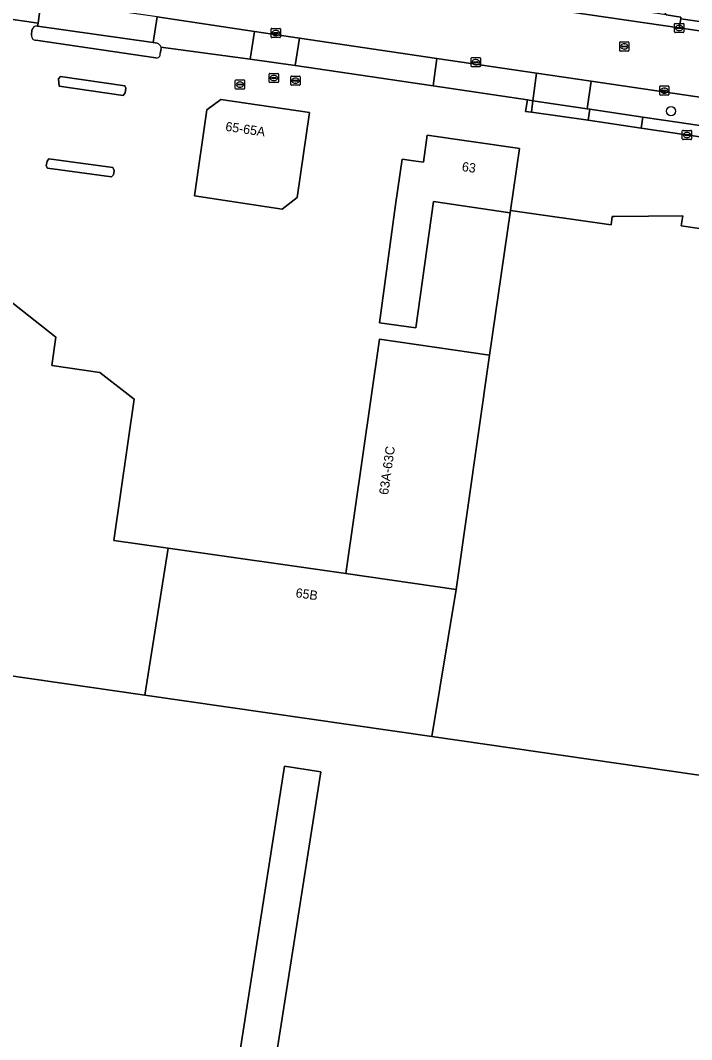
# Model space of a CAD drawing. Extents: x 163683 to 164494, y 382709 to 383872.
# Drawn here: x 163904.3 to 163976.8, y 382819.4 to 382929.4 of the extents above; entities that cross this region are included whole.
import ezdxf

# ---------------------------------------------------------------- set-up
doc = ezdxf.new("R2010")
doc.units = 0
for name, color, linetype in [('IMGEO_Berm_groen', 7, 'Continuous'), ('IMGEO_Boom', 7, 'Continuous'), ('IMGEO_Erf', 7, 'Continuous'), ('IMGEO_Groenvoorziening', 7, 'Continuous'), ('IMGEO_Kolk', 7, 'Continuous'), ('IMGEO_Pand', 7, 'Continuous'), ('IMGEO_Pand_nummerreeks', 7, 'Continuous'), ('IMGEO_Parkeervlak_open', 7, 'Continuous'), ('IMGEO_Rijbaan_lokaal_gesloten', 7, 'Continuous'), ('IMGEO_Rioolput', 7, 'Continuous'), ('IMGEO_Terreindeel_open', 7, 'Continuous'), ('IMGEO_Verkeerseiland_open', 7, 'Continuous'), ('IMGEO_Voetpad_open', 7, 'Continuous')]:
    doc.layers.add(name, color=color, linetype=linetype)

msp = doc.modelspace()

# ---------------------------------------------------------------- linework, layer by layer
at = {"layer": 'IMGEO_Berm_groen'}
msp.add_lwpolyline([(163977.61, 382933.57), (163972.72, 382934.26), (163972.46, 382932.41), (163974.04, 382930.02), (163975.63, 382929.77), (163975.61, 382929.56), (163989.46, 382927.61), (163987.76, 382928.27), (163985.01, 382929.59), (163980.27, 382932.49)], dxfattribs=at)
at = {"layer": 'IMGEO_Boom'}
msp.add_circle((163974.55, 382919.61), 0.489, dxfattribs=at)
at = {"layer": 'IMGEO_Erf'}
for points in [[(163906.13, 382928.79), (163906.23, 382929.1), (163890.65, 382931.38)], [(163905.49, 382927.8), (163905.54, 382928.4)], [(163918.92, 382925.37), (163905.96, 382927.26)], [(163919.49, 382926.34), (163919.38, 382925.85)], [(164013.55, 382911.55), (163971.34, 382917.77), (163965.62, 382918.65), (163959.5, 382919.49), (163958.85, 382919.58), (163959.06, 382920.84), (163948.86, 382922.34), (163933.98, 382924.53), (163929.13, 382925.24), (163919.48, 382926.52)], [(163944.79, 382909.49), (163945.51, 382914.44), (163946.75, 382914.26), (163947.82, 382914.1), (163948.24, 382917.02), (163957.99, 382915.6), (163958.21, 382915.57), (163957.24, 382908.9), (163968.09, 382907.35), (163968.21, 382908.23), (163968.41, 382908.23), (163975.83, 382908.31), (163975.66, 382907.23), (163979.1, 382906.72)], [(163902.97, 382899.27), (163908.12, 382895.2), (163907.71, 382892.14), (163912.87, 382891.39), (163916.57, 382888.53), (163914.4, 382873.28), (163920.25, 382872.44), (163939.45, 382869.7), (163943.07, 382894.99), (163954.97, 382893.26), (163957.2, 382908.65), (163948.9, 382909.85), (163947.02, 382896.22), (163943.07, 382896.77), (163944.79, 382909.49)]]:
    msp.add_lwpolyline(points, dxfattribs=at)
for points in [[(163915.4, 382921.31), (163908.48, 382922.31), (163908.43, 382923.1), (163908.62, 382923.34), (163915.56, 382922.34), (163915.67, 382922.08), (163915.6, 382921.58)], [(163923.11, 382910.46), (163924.45, 382919.77), (163925.94, 382920.88), (163935.52, 382919.48), (163934.18, 382910.29), (163932.55, 382909.05)], [(163914.14, 382912.51), (163907.21, 382913.44), (163907.09, 382913.72), (163907.18, 382914.23), (163907.37, 382914.46), (163914.29, 382913.52), (163914.42, 382913.22), (163914.34, 382912.73)]]:
    msp.add_lwpolyline(points, close=True, dxfattribs=at)
for centre, radius, start, end in [((163906.05, 382928.27), 0.523, 80.6392, 165.5717), ((163906, 382927.76), 0.505, 174.9914, 265.5189), ((163919.05, 382926.42), 0.445, 349.7444, 12.8302), ((163919.03, 382925.73), 0.368, 252.9197, 19.298)]:
    msp.add_arc(centre, radius, start, end, dxfattribs=at)
at = {"layer": 'IMGEO_Groenvoorziening'}
msp.add_lwpolyline([(164000, 382844.71), (163948.74, 382852.1), (163917.73, 382856.57), (163880.83, 382861.88), (163850.77, 382866.24), (163850.46, 382866.29), (163830.96, 382869.23), (163833.62, 382887.2), (163833.33, 382887.25), (163823.99, 382888.59), (163821.09, 382869.09), (163813.85, 382820.4)], dxfattribs=at)
msp.add_lwpolyline([(163932.82, 382848.91), (163936.73, 382848.3), (163931.09, 382812.33), (163927.19, 382812.94)], close=True, dxfattribs=at)
at = {"layer": 'IMGEO_Kolk'}
for p, q in [((163931.38, 382927.62), (163931.38, 382928.48)), ((163931.45, 382928.55), (163932.3, 382928.55)), ((163932.38, 382928.48), (163932.38, 382927.62)), ((163974.93, 382928.16), (163974.93, 382929.02)), ((163975.01, 382929.09), (163975.86, 382929.09)), ((163975.19, 382928.58), (163975.19, 382928.6)), ((163975.63, 382928.55), (163975.23, 382928.55)), ((163975.24, 382928.63), (163975.63, 382928.63)), ((163975.42, 382928.87), (163975.45, 382928.87)), ((163975.68, 382928.6), (163975.68, 382928.58)), ((163975.94, 382929.02), (163975.94, 382928.16)), ((163932.3, 382927.55), (163931.45, 382927.55)), ((163931.64, 382928.04), (163931.64, 382928.06)), ((163931.68, 382928.09), (163932.08, 382928.09)), ((163932.07, 382928.01), (163931.68, 382928.01)), ((163931.89, 382927.77), (163931.86, 382927.77)), ((163931.87, 382928.33), (163931.89, 382928.33)), ((163932.12, 382928.06), (163932.12, 382928.04)), ((163975.86, 382928.09), (163975.01, 382928.09)), ((163975.44, 382928.31), (163975.42, 382928.31)), ((163952.98, 382924.48), (163952.98, 382925.33)), ((163953.05, 382925.4), (163953.9, 382925.4)), ((163953.47, 382925.18), (163953.49, 382925.18)), ((163953.98, 382925.33), (163953.98, 382924.48)), ((163953.9, 382924.4), (163953.05, 382924.4)), ((163953.24, 382924.9), (163953.24, 382924.91)), ((163953.28, 382924.95), (163953.68, 382924.95)), ((163953.67, 382924.86), (163953.28, 382924.86)), ((163953.49, 382924.62), (163953.46, 382924.62)), ((163953.72, 382924.91), (163953.72, 382924.9)), ((163973.34, 382921.4), (163973.34, 382922.26)), ((163973.41, 382922.33), (163974.27, 382922.33)), ((163973.64, 382921.87), (163974.04, 382921.87)), ((163973.83, 382922.11), (163973.85, 382922.11)), ((163974.34, 382922.26), (163974.34, 382921.4)), ((163974.27, 382921.33), (163973.41, 382921.33)), ((163973.6, 382921.82), (163973.6, 382921.84)), ((163974.03, 382921.79), (163973.64, 382921.79)), ((163973.85, 382921.55), (163973.82, 382921.55)), ((163974.08, 382921.84), (163974.08, 382921.82)), ((163975.78, 382916.62), (163975.78, 382917.47)), ((163975.86, 382917.54), (163976.71, 382917.54)), ((163976.78, 382917.47), (163976.78, 382916.62)), ((163976.71, 382916.54), (163975.86, 382916.54)), ((163976.04, 382917.04), (163976.04, 382917.05)), ((163976.48, 382917), (163976.08, 382917)), ((163976.09, 382917.09), (163976.48, 382917.09)), ((163976.27, 382917.32), (163976.3, 382917.32)), ((163976.29, 382916.76), (163976.27, 382916.76)), ((163976.53, 382917.05), (163976.53, 382917.04))]:
    msp.add_line(p, q, dxfattribs=at)
for points in [[(163931.38, 382927.62), (163931.38, 382928.48)], [(163931.45, 382928.55), (163932.3, 382928.55)], [(163932.38, 382928.48), (163932.38, 382927.62)], [(163974.93, 382928.16), (163974.93, 382929.02)], [(163975.01, 382929.09), (163975.86, 382929.09)], [(163975.94, 382929.02), (163975.94, 382928.16)], [(163932.3, 382927.55), (163931.45, 382927.55)], [(163975.86, 382928.09), (163975.01, 382928.09)], [(163952.98, 382924.48), (163952.98, 382925.33)], [(163953.05, 382925.4), (163953.9, 382925.4)], [(163953.98, 382925.33), (163953.98, 382924.48)], [(163953.9, 382924.4), (163953.05, 382924.4)], [(163973.34, 382921.4), (163973.34, 382922.26)], [(163973.41, 382922.33), (163974.27, 382922.33)], [(163974.34, 382922.26), (163974.34, 382921.4)], [(163974.27, 382921.33), (163973.41, 382921.33)], [(163975.78, 382916.62), (163975.78, 382917.47)], [(163975.86, 382917.54), (163976.71, 382917.54)], [(163976.78, 382917.47), (163976.78, 382916.62)], [(163976.71, 382916.54), (163975.86, 382916.54)]]:
    msp.add_lwpolyline(points, dxfattribs=at)
for centre, radius, start, end in [((163931.45, 382928.47), 0.0765, 91.552, 178.448), ((163931.45, 382928.47), 0.0765, 91.552, 178.448), ((163932.3, 382928.47), 0.0765, 1.552, 88.448), ((163932.3, 382928.47), 0.0765, 1.552, 88.448), ((163975.01, 382929.02), 0.0765, 91.552, 178.448), ((163975.01, 382929.02), 0.0765, 91.552, 178.448), ((163975.23, 382928.59), 0.0403, 85.8775, 175.7526), ((163975.23, 382928.58), 0.0366, 178.938, 274.7102), ((163975.64, 382928.6), 0.0386, 1.7309, 96.639), ((163975.63, 382928.59), 0.043, 264.8664, 352.4533), ((163975.86, 382929.02), 0.0765, 1.552, 88.448), ((163975.86, 382929.02), 0.0765, 1.552, 88.448), ((163931.45, 382927.63), 0.0765, 181.552, 268.448), ((163931.45, 382927.63), 0.0765, 181.552, 268.448), ((163931.68, 382928.05), 0.0403, 85.8775, 175.7526), ((163931.67, 382928.04), 0.0366, 178.938, 274.7102), ((163932.08, 382928.05), 0.043, 264.8664, 352.4533), ((163932.08, 382928.05), 0.0386, 1.7309, 96.639), ((163932.3, 382927.63), 0.0765, 271.552, 358.448), ((163932.3, 382927.63), 0.0765, 271.552, 358.448), ((163975.01, 382928.17), 0.0765, 181.552, 268.448), ((163975.01, 382928.17), 0.0765, 181.552, 268.448), ((163975.86, 382928.17), 0.0765, 271.552, 358.448), ((163975.86, 382928.17), 0.0765, 271.552, 358.448), ((163953.05, 382925.33), 0.0765, 91.552, 178.448), ((163953.05, 382925.33), 0.0765, 91.552, 178.448), ((163953.9, 382925.33), 0.0765, 1.552, 88.448), ((163953.9, 382925.33), 0.0765, 1.552, 88.448), ((163953.05, 382924.48), 0.0765, 181.552, 268.448), ((163953.05, 382924.48), 0.0765, 181.552, 268.448), ((163953.28, 382924.91), 0.0403, 85.8775, 175.7526), ((163953.27, 382924.9), 0.0366, 178.938, 274.7102), ((163953.68, 382924.9), 0.043, 264.8664, 352.4533), ((163953.68, 382924.91), 0.0386, 1.7309, 96.639), ((163953.9, 382924.48), 0.0765, 271.552, 358.448), ((163953.9, 382924.48), 0.0765, 271.552, 358.448), ((163973.41, 382922.25), 0.0765, 91.552, 178.448), ((163973.41, 382922.25), 0.0765, 91.552, 178.448), ((163973.64, 382921.83), 0.0403, 85.8775, 175.7526), ((163974.04, 382921.83), 0.0386, 1.7309, 96.639), ((163974.26, 382922.25), 0.0765, 1.552, 88.448), ((163974.26, 382922.25), 0.0765, 1.552, 88.448), ((163973.41, 382921.41), 0.0765, 181.552, 268.448), ((163973.41, 382921.41), 0.0765, 181.552, 268.448), ((163973.63, 382921.82), 0.0366, 178.938, 274.7102), ((163974.04, 382921.83), 0.043, 264.8664, 352.4533), ((163974.26, 382921.41), 0.0765, 271.552, 358.448), ((163974.26, 382921.41), 0.0765, 271.552, 358.448), ((163975.86, 382917.47), 0.0765, 91.552, 178.448), ((163975.86, 382917.47), 0.0765, 91.552, 178.448), ((163976.71, 382917.47), 0.0765, 1.552, 88.448), ((163976.71, 382917.47), 0.0765, 1.552, 88.448), ((163975.86, 382916.62), 0.0765, 181.552, 268.448), ((163975.86, 382916.62), 0.0765, 181.552, 268.448), ((163976.08, 382917.05), 0.0403, 85.8775, 175.7526), ((163976.08, 382917.04), 0.0366, 178.938, 274.7102), ((163976.49, 382917.05), 0.0386, 1.7309, 96.639), ((163976.48, 382917.04), 0.043, 264.8664, 352.4533), ((163976.71, 382916.62), 0.0765, 271.552, 358.448), ((163976.71, 382916.62), 0.0765, 271.552, 358.448)]:
    msp.add_arc(centre, radius, start, end, dxfattribs=at)
for centre, major_axis, ratio, start_param, end_param in [((163975.42, 382928.59), (-0.387, 0.002), 0.722429, 4.712389, 7.853982), ((163975.45, 382928.59), (-0.39, 0.002), 0.717154, 1.570796, 4.712389), ((163931.86, 382928.05), (-0.387, 0.002), 0.722429, 4.712389, 7.853982), ((163931.89, 382928.05), (-0.39, 0.002), 0.717154, 1.570796, 4.712389), ((163953.46, 382924.9), (-0.387, 0.002), 0.722429, 4.712389, 7.853982), ((163953.49, 382924.9), (-0.39, 0.002), 0.717154, 1.570796, 4.712389), ((163973.83, 382921.83), (-0.387, 0.002), 0.722429, 4.712389, 7.853982), ((163973.85, 382921.83), (-0.39, 0.002), 0.717154, 1.570796, 4.712389), ((163976.27, 382917.04), (-0.387, 0.002), 0.722429, 4.712389, 7.853982), ((163976.29, 382917.04), (-0.39, 0.002), 0.717154, 1.570796, 4.712389)]:
    msp.add_ellipse(centre, major_axis=major_axis, ratio=ratio, start_param=start_param, end_param=end_param, dxfattribs=at)
at = {"layer": 'IMGEO_Pand'}
for points in [[(163932.55, 382909.05), (163934.18, 382910.29), (163935.52, 382919.48), (163925.94, 382920.88), (163924.45, 382919.77), (163923.11, 382910.46)], [(163958.21, 382915.57), (163957.99, 382915.6), (163948.24, 382917.02), (163947.82, 382914.1), (163946.75, 382914.26), (163945.51, 382914.44), (163944.79, 382909.49), (163943.07, 382896.77), (163947.02, 382896.22), (163948.9, 382909.85), (163957.2, 382908.65), (163957.24, 382908.9)], [(164012.05, 382900.87), (164000, 382902.64), (163979.22, 382905.69), (163978.95, 382905.73), (163979.1, 382906.72), (163975.66, 382907.23), (163975.83, 382908.31), (163968.41, 382908.23), (163968.21, 382908.23), (163968.09, 382907.35), (163957.24, 382908.9), (163957.2, 382908.65), (163954.97, 382893.26), (163951.34, 382867.97), (163948.74, 382852.1), (164000, 382844.71), (164003.76, 382844.17), (164005.06, 382853.08), (164006.91, 382865.72)], [(163917.73, 382856.57), (163920.25, 382872.44), (163914.4, 382873.28), (163916.57, 382888.53), (163912.87, 382891.39), (163907.71, 382892.14), (163908.12, 382895.2), (163902.97, 382899.27), (163896.74, 382896.84), (163896.27, 382893.82), (163891.18, 382894.5), (163886.72, 382892.72), (163884.5, 382877.5), (163883.13, 382877.69), (163882.41, 382872.74), (163880.83, 382861.88)], [(163939.45, 382869.7), (163951.34, 382867.97), (163954.97, 382893.26), (163943.07, 382894.99)], [(163939.45, 382869.7), (163920.25, 382872.44), (163917.73, 382856.57), (163948.74, 382852.1), (163951.34, 382867.97)]]:
    msp.add_lwpolyline(points, close=True, dxfattribs=at)
at = {"layer": 'IMGEO_Parkeervlak_open'}
for points in [[(163919.07, 382929.78), (163906.56, 382931.62), (163906.23, 382929.1), (163906.13, 382928.79), (163918.64, 382927.02)], [(163934.45, 382927.5), (163929.58, 382928.22), (163929.13, 382925.24), (163933.98, 382924.53)], [(163960.03, 382923.72), (163949.27, 382925.31), (163948.86, 382922.34), (163959.06, 382920.84), (163959.62, 382920.74)]]:
    msp.add_lwpolyline(points, close=True, dxfattribs=at)
msp.add_lwpolyline([(164021.11, 382914.7), (163965.93, 382922.85), (163965.49, 382919.86), (163965.78, 382919.82), (163971.51, 382918.97), (163973.48, 382918.67), (163975.46, 382918.39), (163993.6, 382915.7)], dxfattribs=at)
at = {"layer": 'IMGEO_Rijbaan_lokaal_gesloten'}
msp.add_lwpolyline([(163919.07, 382929.78), (163929.58, 382928.22), (163934.45, 382927.5), (163949.27, 382925.31), (163960.03, 382923.72), (163965.93, 382922.85), (164021.11, 382914.7), (164033.33, 382912.89), (164166.33, 382893.11), (164171.82, 382892.29), (164171.85, 382892.49), (164173.87, 382892.16), (164174.91, 382898.98), (164170.41, 382899.66), (164165.76, 382900.35), (164148.5, 382902.92), (164136.24, 382904.74), (164091.33, 382911.42), (164079.7, 382913.18), (164033.43, 382920.07), (164021.95, 382921.76), (164021.3, 382921.85), (163975.43, 382928.59), (163963.83, 382930.3)], dxfattribs=at)
at = {"layer": 'IMGEO_Rioolput'}
for p, q in [((163969.02, 382926.17), (163969.02, 382927.03)), ((163969.09, 382927.1), (163969.94, 382927.1)), ((163969.27, 382926.59), (163969.27, 382926.61)), ((163969.71, 382926.56), (163969.31, 382926.56)), ((163969.32, 382926.64), (163969.71, 382926.64)), ((163969.5, 382926.88), (163969.53, 382926.88)), ((163969.53, 382926.32), (163969.5, 382926.32)), ((163969.76, 382926.61), (163969.76, 382926.59)), ((163970.02, 382927.03), (163970.02, 382926.17)), ((163969.94, 382926.1), (163969.09, 382926.1)), ((163927.58, 382922.98), (163928.44, 382922.98)), ((163931.16, 382922.76), (163931.16, 382923.61)), ((163931.24, 382923.69), (163932.09, 382923.69)), ((163931.42, 382923.18), (163931.42, 382923.19)), ((163931.86, 382923.14), (163931.46, 382923.14)), ((163931.47, 382923.23), (163931.86, 382923.23)), ((163931.65, 382923.47), (163931.68, 382923.47)), ((163931.91, 382923.19), (163931.91, 382923.18)), ((163932.17, 382923.61), (163932.17, 382922.76)), ((163933.5, 382922.48), (163933.5, 382923.33)), ((163933.57, 382923.4), (163934.43, 382923.4)), ((163933.8, 382922.95), (163934.2, 382922.95)), ((163933.99, 382923.18), (163934.01, 382923.18)), ((163934.5, 382923.33), (163934.5, 382922.48)), ((163927.51, 382922.05), (163927.51, 382922.91)), ((163928.44, 382921.98), (163927.58, 382921.98)), ((163927.77, 382922.47), (163927.77, 382922.49)), ((163927.81, 382922.52), (163928.21, 382922.52)), ((163928.21, 382922.44), (163927.81, 382922.44)), ((163928.02, 382922.2), (163927.99, 382922.2)), ((163928, 382922.76), (163928.02, 382922.76)), ((163928.25, 382922.49), (163928.25, 382922.47)), ((163928.51, 382922.91), (163928.51, 382922.05)), ((163932.09, 382922.69), (163931.24, 382922.69)), ((163931.67, 382922.91), (163931.65, 382922.91)), ((163934.43, 382922.4), (163933.57, 382922.4)), ((163933.76, 382922.9), (163933.76, 382922.91)), ((163934.2, 382922.86), (163933.8, 382922.86)), ((163934.01, 382922.62), (163933.98, 382922.62)), ((163934.24, 382922.91), (163934.24, 382922.9))]:
    msp.add_line(p, q, dxfattribs=at)
for points in [[(163969.02, 382926.17), (163969.02, 382927.03)], [(163969.09, 382927.1), (163969.94, 382927.1)], [(163970.02, 382927.03), (163970.02, 382926.17)], [(163969.94, 382926.1), (163969.09, 382926.1)], [(163927.58, 382922.98), (163928.44, 382922.98)], [(163931.16, 382922.76), (163931.16, 382923.61)], [(163931.24, 382923.69), (163932.09, 382923.69)], [(163932.17, 382923.61), (163932.17, 382922.76)], [(163933.5, 382922.48), (163933.5, 382923.33)], [(163933.57, 382923.4), (163934.43, 382923.4)], [(163934.5, 382923.33), (163934.5, 382922.48)], [(163927.51, 382922.05), (163927.51, 382922.91)], [(163928.44, 382921.98), (163927.58, 382921.98)], [(163928.51, 382922.91), (163928.51, 382922.05)], [(163932.09, 382922.69), (163931.24, 382922.69)], [(163934.43, 382922.4), (163933.57, 382922.4)]]:
    msp.add_lwpolyline(points, dxfattribs=at)
for centre, radius, start, end in [((163969.09, 382927.02), 0.0765, 91.552, 178.448), ((163969.09, 382927.02), 0.0765, 91.552, 178.448), ((163969.31, 382926.6), 0.0403, 85.8775, 175.7526), ((163969.31, 382926.59), 0.0366, 178.938, 274.7102), ((163969.72, 382926.6), 0.0386, 1.7309, 96.639), ((163969.72, 382926.6), 0.043, 264.8664, 352.4533), ((163969.94, 382927.02), 0.0765, 1.552, 88.448), ((163969.94, 382927.02), 0.0765, 1.552, 88.448), ((163969.09, 382926.17), 0.0765, 181.552, 268.448), ((163969.09, 382926.17), 0.0765, 181.552, 268.448), ((163969.94, 382926.17), 0.0765, 271.552, 358.448), ((163969.94, 382926.17), 0.0765, 271.552, 358.448), ((163927.59, 382922.91), 0.0765, 91.552, 178.448), ((163927.59, 382922.91), 0.0765, 91.552, 178.448), ((163928.43, 382922.91), 0.0765, 1.552, 88.448), ((163928.43, 382922.91), 0.0765, 1.552, 88.448), ((163931.24, 382923.61), 0.0765, 91.552, 178.448), ((163931.24, 382923.61), 0.0765, 91.552, 178.448), ((163931.46, 382923.19), 0.0403, 85.8775, 175.7526), ((163931.46, 382923.18), 0.0366, 178.938, 274.7102), ((163931.87, 382923.19), 0.0386, 1.7309, 96.639), ((163931.86, 382923.19), 0.043, 264.8664, 352.4533), ((163932.09, 382923.61), 0.0765, 1.552, 88.448), ((163932.09, 382923.61), 0.0765, 1.552, 88.448), ((163933.58, 382923.33), 0.0765, 91.552, 178.448), ((163933.58, 382923.33), 0.0765, 91.552, 178.448), ((163933.8, 382922.91), 0.0403, 85.8775, 175.7526), ((163934.2, 382922.91), 0.0386, 1.7309, 96.639), ((163934.42, 382923.33), 0.0765, 1.552, 88.448), ((163934.42, 382923.33), 0.0765, 1.552, 88.448), ((163927.59, 382922.06), 0.0765, 181.552, 268.448), ((163927.59, 382922.06), 0.0765, 181.552, 268.448), ((163927.81, 382922.48), 0.0403, 85.8775, 175.7526), ((163927.8, 382922.47), 0.0366, 178.938, 274.7102), ((163928.21, 382922.49), 0.0386, 1.7309, 96.639), ((163928.21, 382922.48), 0.043, 264.8664, 352.4533), ((163928.43, 382922.06), 0.0765, 271.552, 358.448), ((163928.43, 382922.06), 0.0765, 271.552, 358.448), ((163931.24, 382922.76), 0.0765, 181.552, 268.448), ((163931.24, 382922.76), 0.0765, 181.552, 268.448), ((163932.09, 382922.76), 0.0765, 271.552, 358.448), ((163932.09, 382922.76), 0.0765, 271.552, 358.448), ((163933.58, 382922.48), 0.0765, 181.552, 268.448), ((163933.58, 382922.48), 0.0765, 181.552, 268.448), ((163933.79, 382922.9), 0.0366, 178.938, 274.7102), ((163934.2, 382922.9), 0.043, 264.8664, 352.4533), ((163934.42, 382922.48), 0.0765, 271.552, 358.448), ((163934.42, 382922.48), 0.0765, 271.552, 358.448)]:
    msp.add_arc(centre, radius, start, end, dxfattribs=at)
for centre, major_axis, ratio, start_param, end_param in [((163969.5, 382926.6), (-0.387, 0.002), 0.722429, 4.712389, 7.853982), ((163969.53, 382926.6), (-0.39, 0.002), 0.717154, 1.570796, 4.712389), ((163931.65, 382923.19), (-0.387, 0.002), 0.722429, 4.712389, 7.853982), ((163931.68, 382923.19), (-0.39, 0.002), 0.717154, 1.570796, 4.712389), ((163933.99, 382922.9), (-0.387, 0.002), 0.722429, 4.712389, 7.853982), ((163934.01, 382922.9), (-0.39, 0.002), 0.717154, 1.570796, 4.712389), ((163928, 382922.48), (-0.387, 0.002), 0.722429, 4.712389, 7.853982), ((163928.02, 382922.48), (-0.39, 0.002), 0.717154, 1.570796, 4.712389)]:
    msp.add_ellipse(centre, major_axis=major_axis, ratio=ratio, start_param=start_param, end_param=end_param, dxfattribs=at)
at = {"layer": 'IMGEO_Terreindeel_open'}
msp.add_lwpolyline([(163927.19, 382812.94), (163931.09, 382812.33), (163936.73, 382848.3), (163932.82, 382848.91)], close=True, dxfattribs=at)
at = {"layer": 'IMGEO_Verkeerseiland_open'}
for points in [[(163919.07, 382926.96), (163918.64, 382927.02), (163906.13, 382928.79)], [(163905.54, 382928.4), (163905.49, 382927.8)], [(163905.96, 382927.26), (163918.92, 382925.37)], [(163919.38, 382925.85), (163919.49, 382926.34)]]:
    msp.add_lwpolyline(points, dxfattribs=at)
for points in [[(163915.6, 382921.58), (163915.67, 382922.08), (163915.56, 382922.34), (163908.62, 382923.34), (163908.43, 382923.1), (163908.48, 382922.31), (163915.4, 382921.31)], [(163914.34, 382912.73), (163914.42, 382913.22), (163914.29, 382913.52), (163907.37, 382914.46), (163907.18, 382914.23), (163907.09, 382913.72), (163907.21, 382913.44), (163914.14, 382912.51)]]:
    msp.add_lwpolyline(points, close=True, dxfattribs=at)
for centre, radius, start, end in [((163906.05, 382928.27), 0.523, 80.6392, 165.5717), ((163906, 382927.76), 0.505, 174.9914, 265.5189), ((163918.77, 382926.26), 0.76, 19.632, 66.6211), ((163919.05, 382926.42), 0.445, 349.7444, 12.8302), ((163919.03, 382925.73), 0.368, 252.9197, 19.298)]:
    msp.add_arc(centre, radius, start, end, dxfattribs=at)
at = {"layer": 'IMGEO_Voetpad_open'}
for points in [[(163906.59, 382931.88), (163891.02, 382934.19), (163890.65, 382931.38), (163906.23, 382929.1), (163906.56, 382931.62)], [(163964, 382931.48), (163963.96, 382931.29), (163963.83, 382930.3), (163975.43, 382928.59), (163975.61, 382929.56), (163975.63, 382929.77), (163974.04, 382930.02), (163965.67, 382931.23)], [(163975.43, 382928.59), (164021.3, 382921.85), (164021.44, 382922.8), (164004.31, 382925.42), (163989.46, 382927.61), (163975.61, 382929.56)], [(163949.27, 382925.31), (163934.45, 382927.5), (163933.98, 382924.53), (163948.86, 382922.34)], [(163965.93, 382922.85), (163960.03, 382923.72), (163959.62, 382920.74), (163965.49, 382919.86)], [(163959.62, 382920.74), (163959.06, 382920.84), (163958.85, 382919.58), (163959.5, 382919.49)], [(163965.78, 382919.82), (163965.49, 382919.86), (163959.62, 382920.74), (163959.5, 382919.49), (163965.62, 382918.65)], [(163965.78, 382919.82), (163965.62, 382918.65), (163971.34, 382917.77), (163971.51, 382918.97)], [(163971.34, 382917.77), (164013.55, 382911.55), (164014.36, 382911.43), (164014.54, 382912.6), (164013.24, 382912.82), (164011.29, 382913.2), (163995.7, 382915.39), (163993.6, 382915.7), (163975.46, 382918.39), (163973.48, 382918.67), (163971.51, 382918.97)]]:
    msp.add_lwpolyline(points, close=True, dxfattribs=at)
for points in [[(163929.58, 382928.22), (163919.07, 382929.78), (163918.64, 382927.02), (163919.07, 382926.96)], [(163919.48, 382926.52), (163929.13, 382925.24), (163929.58, 382928.22)]]:
    msp.add_lwpolyline(points, dxfattribs=at)
msp.add_arc((163918.77, 382926.26), 0.76, 19.632, 66.6211, dxfattribs=at)

# ---------------------------------------------------------------- texts
at = {"layer": 'IMGEO_Pand_nummerreeks'}
for s, rotation, p in [('65-65A', 351.734, (163926.39, 382917.49)), ('63', 351.7347, (163951.93, 382913.16)), ('63A-63C', 81.8141, (163944.01, 382878.15)), ('65B', 351.8145, (163933.98, 382867.15))]:
    msp.add_text(s, height=1, rotation=rotation, dxfattribs=at).set_placement(p)

doc.saveas('drawing.dxf')
